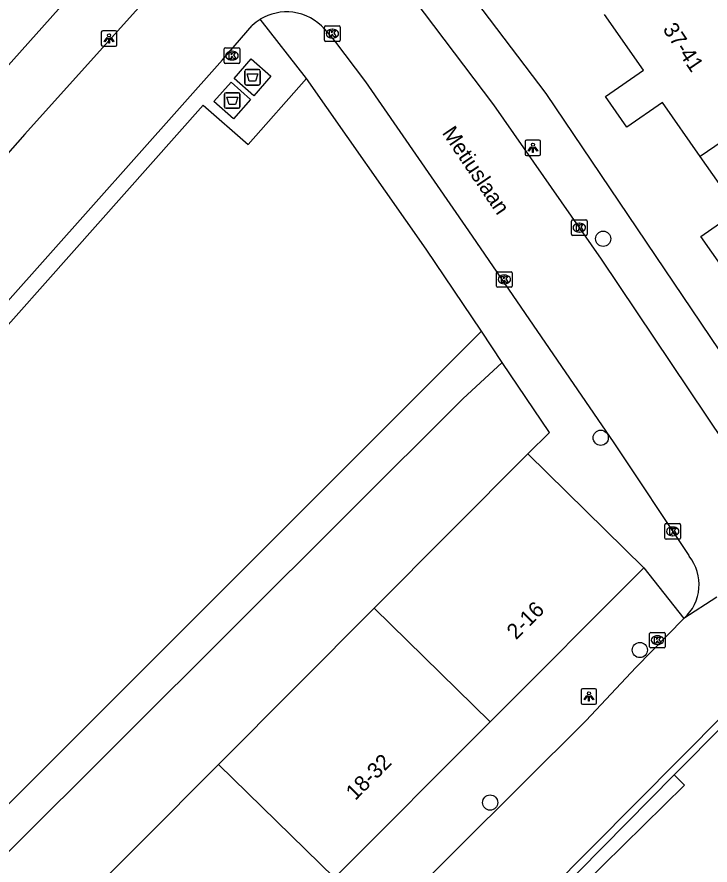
# Model space of a CAD drawing. Extents: x 159888 to 160757, y 384031 to 384746.
# Drawn here: x 160372.9 to 160417.5, y 384284.5 to 384339.1 of the extents above; entities that cross this region are included whole.
import ezdxf

# ---------------------------------------------------------------- set-up
doc = ezdxf.new("R2010")
doc.units = 0
for name, color, linetype in [('IMGEO_Afval_apart_plaats', 7, 'Continuous'), ('IMGEO_Boom', 7, 'Continuous'), ('IMGEO_Kolk', 7, 'Continuous'), ('IMGEO_Lichtpunt', 7, 'Continuous'), ('IMGEO_Openbare_ruimte_label', 7, 'Continuous'), ('IMGEO_Pand', 7, 'Continuous'), ('IMGEO_Pand_nummerreeks', 7, 'Continuous'), ('IMGEO_Rijbaan_lokaal_open', 7, 'Continuous'), ('IMGEO_Voetpad_gesloten', 7, 'Continuous'), ('IMGEO_Voetpad_halfverhard', 7, 'Continuous'), ('IMGEO_Voetpad_open', 7, 'Continuous')]:
    doc.layers.add(name, color=color, linetype=linetype)

msp = doc.modelspace()

# ---------------------------------------------------------------- linework, layer by layer
at = {"layer": 'IMGEO_Afval_apart_plaats'}
for p, q in [((160387.521, 384334.829), (160387.521, 384335.629)), ((160387.521, 384335.629), (160387.521, 384334.829)), ((160387.621, 384335.729), (160388.411, 384335.729)), ((160388.411, 384335.729), (160387.621, 384335.729)), ((160388.511, 384335.629), (160388.511, 384334.829)), ((160388.511, 384334.829), (160388.511, 384335.629)), ((160388.411, 384334.729), (160387.621, 384334.729)), ((160387.621, 384334.729), (160388.411, 384334.729)), ((160386.216, 384333.339), (160386.216, 384334.139)), ((160386.216, 384334.139), (160386.216, 384333.339)), ((160386.316, 384334.239), (160387.106, 384334.239)), ((160387.106, 384334.239), (160386.316, 384334.239)), ((160387.206, 384334.139), (160387.206, 384333.339)), ((160387.206, 384333.339), (160387.206, 384334.139)), ((160387.106, 384333.239), (160386.316, 384333.239)), ((160386.316, 384333.239), (160387.106, 384333.239))]:
    msp.add_line(p, q, dxfattribs=at)
for points in [[(160387.664, 384335.443), (160388.368, 384335.443), (160388.219, 384334.973), (160387.813, 384334.973), (160387.664, 384335.443)], [(160386.359, 384333.953), (160387.063, 384333.953), (160386.914, 384333.483), (160386.508, 384333.483), (160386.359, 384333.953)]]:
    msp.add_lwpolyline(points, dxfattribs=at)
for centre, start, end in [((160387.621, 384335.629), 90, 180), ((160387.621, 384335.629), 90, 180), ((160388.411, 384335.629), 0, 90), ((160388.411, 384335.629), 360, 90), ((160387.621, 384334.829), 180, 270), ((160387.621, 384334.829), 180, 270), ((160388.411, 384334.829), 270, 0), ((160388.411, 384334.829), 270, 0), ((160386.316, 384334.139), 90, 180), ((160386.316, 384334.139), 90, 180), ((160387.106, 384334.139), 0, 90), ((160387.106, 384334.139), 360, 90), ((160386.316, 384333.339), 180, 270), ((160386.316, 384333.339), 180, 270), ((160387.106, 384333.339), 270, 0), ((160387.106, 384333.339), 270, 0)]:
    msp.add_arc(centre, 0.1, start, end, dxfattribs=at)
at = {"layer": 'IMGEO_Boom'}
for centre in [(160410.598, 384324.838), (160410.441, 384312.035), (160412.962, 384298.376), (160403.319, 384288.557)]:
    msp.add_circle(centre, 0.489, dxfattribs=at)
at = {"layer": 'IMGEO_Kolk'}
for p, q in [((160392.661, 384337.61), (160392.661, 384338.462)), ((160392.736, 384338.536), (160393.588, 384338.536)), ((160393.149, 384338.316), (160393.174, 384338.316)), ((160393.662, 384338.462), (160393.662, 384337.61)), ((160393.172, 384337.756), (160393.147, 384337.756)), ((160386.196, 384336.199), (160386.196, 384337.051)), ((160386.271, 384337.125), (160387.123, 384337.125)), ((160387.197, 384337.051), (160387.197, 384336.199)), ((160393.588, 384337.536), (160392.736, 384337.536)), ((160386.684, 384336.905), (160386.709, 384336.905)), ((160387.123, 384336.125), (160386.271, 384336.125)), ((160386.707, 384336.345), (160386.682, 384336.345)), ((160408.56, 384325.127), (160408.56, 384325.979)), ((160408.635, 384326.053), (160409.487, 384326.053)), ((160409.048, 384325.833), (160409.073, 384325.833)), ((160409.561, 384325.979), (160409.561, 384325.127)), ((160409.487, 384325.053), (160408.635, 384325.053)), ((160409.071, 384325.273), (160409.046, 384325.273)), ((160403.737, 384321.795), (160403.737, 384322.647)), ((160403.812, 384322.721), (160404.664, 384322.721)), ((160404.225, 384322.501), (160404.25, 384322.501)), ((160404.738, 384322.647), (160404.738, 384321.795)), ((160404.248, 384321.941), (160404.223, 384321.941)), ((160404.664, 384321.721), (160403.812, 384321.721)), ((160414.649, 384306.507), (160415.501, 384306.507)), ((160414.574, 384305.581), (160414.574, 384306.433)), ((160415.062, 384306.287), (160415.087, 384306.287)), ((160415.575, 384306.433), (160415.575, 384305.581)), ((160415.501, 384305.507), (160414.649, 384305.507)), ((160415.085, 384305.727), (160415.06, 384305.727)), ((160413.591, 384298.585), (160413.591, 384299.437)), ((160413.666, 384299.511), (160414.518, 384299.511)), ((160414.592, 384299.437), (160414.592, 384298.585)), ((160414.079, 384299.291), (160414.104, 384299.291)), ((160414.518, 384298.511), (160413.666, 384298.511)), ((160414.102, 384298.731), (160414.077, 384298.731))]:
    msp.add_line(p, q, dxfattribs=at)
for points in [[(160392.661, 384337.61), (160392.661, 384338.462)], [(160392.736, 384338.536), (160393.588, 384338.536)], [(160392.982, 384338.236), (160393.105, 384338.236), (160393.105, 384338.085), (160393.235, 384338.236), (160393.399, 384338.236), (160393.253, 384338.085), (160393.406, 384337.836), (160393.254, 384337.836), (160393.169, 384338), (160393.105, 384337.933), (160393.105, 384337.836), (160392.982, 384337.836), (160392.982, 384338.236)], [(160393.662, 384338.462), (160393.662, 384337.61)], [(160386.196, 384336.199), (160386.196, 384337.051)], [(160386.271, 384337.125), (160387.123, 384337.125)], [(160387.197, 384337.051), (160387.197, 384336.199)], [(160393.588, 384337.536), (160392.736, 384337.536)], [(160386.517, 384336.825), (160386.64, 384336.825), (160386.64, 384336.674), (160386.77, 384336.825), (160386.934, 384336.825), (160386.788, 384336.674), (160386.941, 384336.425), (160386.789, 384336.425), (160386.704, 384336.589), (160386.64, 384336.522), (160386.64, 384336.425), (160386.517, 384336.425), (160386.517, 384336.825)], [(160387.123, 384336.125), (160386.271, 384336.125)], [(160408.56, 384325.127), (160408.56, 384325.979)], [(160408.635, 384326.053), (160409.487, 384326.053)], [(160408.881, 384325.753), (160409.004, 384325.753), (160409.004, 384325.602), (160409.134, 384325.753), (160409.298, 384325.753), (160409.152, 384325.602), (160409.305, 384325.353), (160409.153, 384325.353), (160409.068, 384325.517), (160409.004, 384325.45), (160409.004, 384325.353), (160408.881, 384325.353), (160408.881, 384325.753)], [(160409.561, 384325.979), (160409.561, 384325.127)], [(160409.487, 384325.053), (160408.635, 384325.053)], [(160403.737, 384321.795), (160403.737, 384322.647)], [(160403.812, 384322.721), (160404.664, 384322.721)], [(160404.058, 384322.421), (160404.181, 384322.421), (160404.181, 384322.27), (160404.311, 384322.421), (160404.475, 384322.421), (160404.329, 384322.27), (160404.482, 384322.021), (160404.33, 384322.021), (160404.245, 384322.185), (160404.181, 384322.118), (160404.181, 384322.021), (160404.058, 384322.021), (160404.058, 384322.421)], [(160404.738, 384322.647), (160404.738, 384321.795)], [(160404.664, 384321.721), (160403.812, 384321.721)], [(160414.649, 384306.507), (160415.501, 384306.507)], [(160414.574, 384305.581), (160414.574, 384306.433)], [(160414.895, 384306.207), (160415.018, 384306.207), (160415.018, 384306.056), (160415.148, 384306.207), (160415.312, 384306.207), (160415.166, 384306.056), (160415.319, 384305.807), (160415.167, 384305.807), (160415.082, 384305.971), (160415.018, 384305.904), (160415.018, 384305.807), (160414.895, 384305.807), (160414.895, 384306.207)], [(160415.575, 384306.433), (160415.575, 384305.581)], [(160415.501, 384305.507), (160414.649, 384305.507)], [(160413.591, 384298.585), (160413.591, 384299.437)], [(160413.666, 384299.511), (160414.518, 384299.511)], [(160414.592, 384299.437), (160414.592, 384298.585)], [(160413.912, 384299.211), (160414.035, 384299.211), (160414.035, 384299.06), (160414.165, 384299.211), (160414.329, 384299.211), (160414.183, 384299.06), (160414.336, 384298.811), (160414.184, 384298.811), (160414.099, 384298.975), (160414.035, 384298.908), (160414.035, 384298.811), (160413.912, 384298.811), (160413.912, 384299.211)], [(160414.518, 384298.511), (160413.666, 384298.511)]]:
    msp.add_lwpolyline(points, dxfattribs=at)
for centre, start, end in [((160392.738, 384338.46), 91.552, 178.448), ((160392.738, 384338.46), 91.552, 178.448), ((160393.586, 384338.46), 1.552, 88.448), ((160393.586, 384338.46), 1.552, 88.448), ((160392.738, 384337.612), 181.552, 268.448), ((160392.738, 384337.612), 181.552, 268.448), ((160393.586, 384337.612), 271.552, 358.448), ((160393.586, 384337.612), 271.552, 358.448), ((160386.273, 384337.049), 91.552, 178.448), ((160386.273, 384337.049), 91.552, 178.448), ((160387.121, 384337.049), 1.552, 88.448), ((160387.121, 384337.049), 1.552, 88.448), ((160386.273, 384336.201), 181.552, 268.448), ((160386.273, 384336.201), 181.552, 268.448), ((160387.121, 384336.201), 271.552, 358.448), ((160387.121, 384336.201), 271.552, 358.448), ((160408.637, 384325.977), 91.552, 178.448), ((160408.637, 384325.977), 91.552, 178.448), ((160409.485, 384325.977), 1.552, 88.448), ((160409.485, 384325.977), 1.552, 88.448), ((160408.637, 384325.129), 181.552, 268.448), ((160408.637, 384325.129), 181.552, 268.448), ((160409.485, 384325.129), 271.552, 358.448), ((160409.485, 384325.129), 271.552, 358.448), ((160403.814, 384322.645), 91.552, 178.448), ((160403.814, 384322.645), 91.552, 178.448), ((160404.662, 384322.645), 1.552, 88.448), ((160404.662, 384322.645), 1.552, 88.448), ((160403.814, 384321.797), 181.552, 268.448), ((160403.814, 384321.797), 181.552, 268.448), ((160404.662, 384321.797), 271.552, 358.448), ((160404.662, 384321.797), 271.552, 358.448), ((160414.651, 384306.431), 91.552, 178.448), ((160414.651, 384306.431), 91.552, 178.448), ((160415.499, 384306.431), 1.552, 88.448), ((160415.499, 384306.431), 1.552, 88.448), ((160414.651, 384305.583), 181.552, 268.448), ((160414.651, 384305.583), 181.552, 268.448), ((160415.499, 384305.583), 271.552, 358.448), ((160415.499, 384305.583), 271.552, 358.448), ((160413.668, 384299.435), 91.552, 178.448), ((160413.668, 384299.435), 91.552, 178.448), ((160414.516, 384299.435), 1.552, 88.448), ((160414.516, 384299.435), 1.552, 88.448), ((160413.668, 384298.587), 181.552, 268.448), ((160413.668, 384298.587), 181.552, 268.448), ((160414.516, 384298.587), 271.552, 358.448), ((160414.516, 384298.587), 271.552, 358.448)]:
    msp.add_arc(centre, 0.0765, start, end, dxfattribs=at)
for centre, major_axis, ratio, start_param, end_param in [((160393.148, 384338.036), (-0.387, 0.002), 0.722429, 4.712389, 7.853982), ((160393.173, 384338.036), (-0.39, 0.002), 0.717154, 1.570796, 4.712389), ((160386.683, 384336.625), (-0.387, 0.002), 0.722429, 4.712389, 7.853982), ((160386.708, 384336.625), (-0.39, 0.002), 0.717154, 1.570796, 4.712389), ((160409.047, 384325.553), (-0.387, 0.002), 0.722429, 4.712389, 7.853982), ((160409.072, 384325.553), (-0.39, 0.002), 0.717154, 1.570796, 4.712389), ((160404.224, 384322.221), (-0.387, 0.002), 0.722429, 4.712389, 7.853982), ((160404.249, 384322.221), (-0.39, 0.002), 0.717154, 1.570796, 4.712389), ((160415.061, 384306.007), (-0.387, 0.002), 0.722429, 4.712389, 7.853982), ((160415.086, 384306.007), (-0.39, 0.002), 0.717154, 1.570796, 4.712389), ((160414.078, 384299.011), (-0.387, 0.002), 0.722429, 4.712389, 7.853982), ((160414.103, 384299.011), (-0.39, 0.002), 0.717154, 1.570796, 4.712389)]:
    msp.add_ellipse(centre, major_axis=major_axis, ratio=ratio, start_param=start_param, end_param=end_param, dxfattribs=at)
at = {"layer": 'IMGEO_Lichtpunt'}
for p, q in [((160378.284, 384338.133), (160378.284, 384337.326)), ((160378.284, 384338.133), (160378.284, 384337.326)), ((160379.186, 384338.228), (160378.378, 384338.228)), ((160379.186, 384338.228), (160378.378, 384338.228)), ((160379.28, 384337.326), (160379.28, 384338.133)), ((160379.28, 384337.326), (160379.28, 384338.133)), ((160378.378, 384337.232), (160379.186, 384337.232)), ((160378.378, 384337.232), (160379.186, 384337.232)), ((160405.576, 384331.099), (160405.576, 384330.292)), ((160405.576, 384331.099), (160405.576, 384330.292)), ((160406.478, 384331.194), (160405.67, 384331.194)), ((160406.478, 384331.194), (160405.67, 384331.194)), ((160406.572, 384330.292), (160406.572, 384331.099)), ((160406.572, 384330.292), (160406.572, 384331.099)), ((160405.67, 384330.198), (160406.478, 384330.198)), ((160405.67, 384330.198), (160406.478, 384330.198)), ((160409.181, 384295.788), (160409.181, 384294.981)), ((160409.181, 384295.788), (160409.181, 384294.981)), ((160410.083, 384295.883), (160409.275, 384295.883)), ((160410.083, 384295.883), (160409.275, 384295.883)), ((160410.177, 384294.981), (160410.177, 384295.788)), ((160410.177, 384294.981), (160410.177, 384295.788)), ((160409.275, 384294.887), (160410.083, 384294.887)), ((160409.275, 384294.887), (160410.083, 384294.887))]:
    msp.add_line(p, q, dxfattribs=at)
for points in [[(160378.658, 384337.797), (160378.697, 384337.769), (160378.509, 384337.507), (160378.471, 384337.534), (160378.658, 384337.797)], [(160378.76, 384337.749), (160378.807, 384337.749), (160378.807, 384337.427), (160378.76, 384337.427), (160378.76, 384337.749)], [(160378.87, 384337.769), (160378.908, 384337.796), (160379.095, 384337.534), (160379.056, 384337.506), (160378.87, 384337.769)], [(160405.95, 384330.763), (160405.989, 384330.735), (160405.801, 384330.473), (160405.763, 384330.5), (160405.95, 384330.763)], [(160406.052, 384330.715), (160406.099, 384330.715), (160406.099, 384330.393), (160406.052, 384330.393), (160406.052, 384330.715)], [(160406.162, 384330.735), (160406.2, 384330.762), (160406.387, 384330.5), (160406.348, 384330.472), (160406.162, 384330.735)], [(160409.555, 384295.452), (160409.594, 384295.424), (160409.406, 384295.162), (160409.368, 384295.189), (160409.555, 384295.452)], [(160409.657, 384295.404), (160409.704, 384295.404), (160409.704, 384295.082), (160409.657, 384295.082), (160409.657, 384295.404)], [(160409.767, 384295.424), (160409.805, 384295.451), (160409.992, 384295.189), (160409.953, 384295.161), (160409.767, 384295.424)]]:
    msp.add_lwpolyline(points, dxfattribs=at)
for centre in [(160378.783, 384337.931), (160406.075, 384330.897), (160409.68, 384295.586)]:
    msp.add_circle(centre, 0.0994, dxfattribs=at)
for centre, start, end in [((160378.378, 384338.133), 90, 180), ((160378.378, 384338.133), 90, 180), ((160379.186, 384338.133), 0, 90), ((160379.186, 384338.133), 0, 90), ((160378.378, 384337.326), 180, 270), ((160378.378, 384337.326), 180, 270), ((160379.186, 384337.326), 270, 0), ((160379.186, 384337.326), 270, 360), ((160405.67, 384331.099), 90, 180), ((160405.67, 384331.099), 90, 180), ((160406.478, 384331.099), 0, 90), ((160406.478, 384331.099), 0, 90), ((160405.67, 384330.292), 180, 270), ((160405.67, 384330.292), 180, 270), ((160406.478, 384330.292), 270, 0), ((160406.478, 384330.292), 270, 360), ((160409.275, 384295.788), 90, 180), ((160409.275, 384295.788), 90, 180), ((160410.083, 384295.788), 0, 90), ((160410.083, 384295.788), 0, 90), ((160409.275, 384294.981), 180, 270), ((160409.275, 384294.981), 180, 270), ((160410.083, 384294.981), 270, 0), ((160410.083, 384294.981), 270, 360)]:
    msp.add_arc(centre, 0.0946, start, end, dxfattribs=at)
at = {"layer": 'IMGEO_Pand'}
for points in [[(160381.45, 384346.268), (160372.116, 384335.798)], [(160416.848, 384330.131), (160414.413, 384333.61), (160412.132, 384332.013), (160410.75, 384333.987), (160413.186, 384335.692), (160410.686, 384339.264)], [(160424.065, 384335.047), (160416.848, 384330.131)], [(160423.041, 384321.035), (160420.578, 384324.555), (160418.299, 384322.96), (160416.889, 384324.975), (160419.284, 384326.651), (160416.848, 384330.131)], [(160405.753, 384310.998), (160395.852, 384301.068)], [(160413.221, 384303.667), (160405.753, 384310.998)], [(160403.325, 384293.755), (160413.221, 384303.667)], [(160395.852, 384301.068), (160385.826, 384291.012)], [(160395.852, 384301.068), (160403.325, 384293.755)], [(160393.291, 384283.706), (160403.325, 384293.755)], [(160385.826, 384291.012), (160375.799, 384280.956)], [(160393.291, 384283.706), (160385.826, 384291.012)]]:
    msp.add_lwpolyline(points, dxfattribs=at)
at = {"layer": 'IMGEO_Rijbaan_lokaal_open'}
for points in [[(160359.665, 384386.419), (160363.379, 384382.068), (160379.601, 384362.826), (160397.147, 384341.932), (160403.531, 384333.459), (160410.478, 384323.524), (160422.888, 384305.012)], [(160383.963, 384343.377), (160373.369, 384331.56), (160358.734, 384315.005), (160355.836, 384311.606), (160354.645, 384310.274), (160345.783, 384300.371), (160342.137, 384296.259), (160335.028, 384288.426)], [(160319.303, 384267.551), (160320.163, 384268.187), (160325.613, 384272.322), (160329.833, 384275.348), (160333.576, 384278.079), (160335.984, 384279.983), (160336.104, 384280.105), (160336.716, 384280.731), (160338.331, 384282.617), (160345.01, 384289.972), (160361.399, 384308.557), (160367.398, 384315.345), (160372.06, 384320.608), (160386.091, 384336.349), (160387.995, 384338.559)], [(160392.662, 384338.322), (160393.299, 384337.568), (160395.286, 384334.93), (160401.919, 384325.35), (160411.295, 384311.705), (160416.108, 384304.452), (160416.132, 384304.416)], [(160417.91, 384301.776), (160415.801, 384300.405)], [(160415.801, 384300.405), (160412.696, 384297.247), (160409.504, 384293.847), (160396.973, 384281.372), (160379.726, 384264.338), (160372.559, 384257.094), (160366.063, 384250.659), (160365.342, 384250), (160363.109, 384247.959)], [(160346.326, 384226.816), (160346.553, 384226.989), (160354.699, 384232.863), (160360.784, 384237.351), (160361.189, 384237.649), (160363.689, 384239.781), (160364.647, 384240.62), (160366.673, 384242.576), (160373.037, 384248.641), (160374.399, 384250), (160384.224, 384259.805), (160390.609, 384266.27), (160401.354, 384277.085), (160418.41, 384294.276)]]:
    msp.add_lwpolyline(points, dxfattribs=at)
for centre, radius, start, end in [((160390.213, 384336.199), 3.238, 82.7465, 121.5249), ((160390.217, 384336.197), 3.239, 40.9932, 82.8181), ((160390.138, 384336.291), 3.12, 121.2332, 133.3747), ((160413.852, 384302.585), 2.924, 311.8023, 38.7627)]:
    msp.add_arc(centre, radius, start, end, dxfattribs=at)
at = {"layer": 'IMGEO_Voetpad_gesloten'}
for points in [[(160386.832, 384335.161), (160387.936, 384336.412), (160389.2, 384335.297), (160388.096, 384334.046), (160386.832, 384335.161)], [(160385.526, 384333.668), (160386.637, 384334.924), (160387.896, 384333.81), (160386.785, 384332.554), (160385.526, 384333.668)]]:
    msp.add_lwpolyline(points, dxfattribs=at)
at = {"layer": 'IMGEO_Voetpad_halfverhard'}
for points in [[(160402.753, 384318.884), (160371.557, 384287.736), (160362.749, 384287.577), (160362.609, 384308.421)], [(160362.772, 384285.007), (160372.039, 384285.135), (160401.57, 384314.532), (160404.095, 384316.885)]]:
    msp.add_lwpolyline(points, dxfattribs=at)
at = {"layer": 'IMGEO_Voetpad_open'}
for points in [[(160354.946, 384397.526), (160354.597, 384397.082), (160401.024, 384341.943), (160406.906, 384334.176), (160430.378, 384299.406)], [(160391.497, 384335.159), (160388.52, 384338.959)], [(160362.609, 384308.421), (160384.849, 384333.43), (160387.746, 384330.904), (160391.497, 384335.159)], [(160402.753, 384318.884), (160399.209, 384324.159), (160391.497, 384335.159)], [(160404.095, 384316.885), (160402.753, 384318.884)], [(160405.753, 384310.998), (160407.134, 384312.362), (160404.095, 384316.885)], [(160413.221, 384303.667), (160415.801, 384300.405)], [(160415.176, 384290.342), (160418.424, 384293.635)], [(160395.281, 384270.172), (160415.176, 384290.342)], [(160415.176, 384290.342), (160415.838, 384289.689), (160407.979, 384281.961), (160396.416, 384270.415), (160395.73, 384269.729), (160395.281, 384270.172)]]:
    msp.add_lwpolyline(points, dxfattribs=at)

# ---------------------------------------------------------------- texts
at = {"layer": 'IMGEO_Openbare_ruimte_label'}
msp.add_text('Metiuslaan', height=1, rotation=304.0395, dxfattribs=at).set_placement((160400.192, 384331.652))
at = {"layer": 'IMGEO_Pand_nummerreeks'}
for s, rotation, p in [('37-41', 303.7642, (160414.399, 384338.321)), ('2-16', 45, (160404.988, 384298.995)), ('18-32', 45.1059, (160394.633, 384288.652))]:
    msp.add_text(s, height=1, rotation=rotation, dxfattribs=at).set_placement(p)

doc.saveas('drawing.dxf')
